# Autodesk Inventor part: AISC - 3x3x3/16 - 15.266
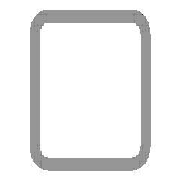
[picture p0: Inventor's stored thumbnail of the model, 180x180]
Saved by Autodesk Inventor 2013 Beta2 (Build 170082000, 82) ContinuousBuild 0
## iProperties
IsCustomPart: 1
Created: 2011-01
Part Number: AISC - 3x3x3/16 - 15.266
Material: Steel, Mild
Description: Tube
Document SubType Name: Modeling
Standard: ANSI
Designer: Beta-8540w
Standards Organization: ANSI
Language: en-US
Size Designation: 3x3x3/16
Categories: <MemberInstance><Categories><Category DisplayName="Structural Shapes" InternalName="089c4875-fa83-4c05-b084-43b9cc11f5ed" Mnemonic="GRDR"><CategoryParameter Dis
Stock Number: 3x3x3/16
Density: 7.86 g/cm^3
_CCFamilyMember: 9
_CCFamilyDisplayName: ANSI AISC (Square) - Tube
_FrameMemberDoc: Frame Member File
_Version: 15.0.0
_GetPNFromCC: 1
G_L: 15.266 in
G_W: 3.000 in
G_H: 3.000 in
+FD2FA98F-6131-4ED7-8715-576CB225FAC2+CUTDETAIL1: Cut
+6EE38D32-1A45-4B16-9B4C-47EFE8477959+CUTDETAIL2: Cut
Author: Beta-8540w
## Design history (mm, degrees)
node "Start plane"
node "End plane"
sketch "Sketch"
  geometry: L1 (-38.1, -28.575)-(-38.1, 28.575); L2 (-28.575, 38.1)-(28.575, 38.1); L3 (38.1, 28.575)-(38.1, -28.575); L4 (28.575, -38.1)-(-28.575, -38.1); L5 (-28.575, 33.337)-(28.575, 33.338); L6 (33.338, 28.575)-(33.338, -28.575); L7 (28.575, -33.337)-(-28.575, -33.338); L8 (-33.338, -28.575)-(-33.338, 28.575); L9 (0, 56.102)-(0, -56.102) reference; L10 (-56.102, 0)-(56.102, 0) reference; A1 r 9.525 centre (-28.575, -28.575) between (-38.1, -28.575) and (-28.575, -38.1); A2 r 9.525 centre (-28.575, 28.575) between (-28.575, 38.1) and (-38.1, 28.575); A3 r 9.525 centre (28.575, 28.575) between (38.1, 28.575) and (28.575, 38.1); A4 r 9.525 centre (28.575, -28.575) between (28.575, -38.1) and (38.1, -28.575); A5 r 4.763 centre (-28.575, 28.575) between (-28.575, 33.337) and (-33.338, 28.575); A6 r 4.763 centre (28.575, 28.575) between (33.338, 28.575) and (28.575, 33.338); A7 r 4.763 centre (28.575, -28.575) between (28.575, -33.337) and (33.338, -28.575); A8 r 4.763 centre (-28.575, -28.575) between (-33.338, -28.575) and (-28.575, -33.338)
  constraints: 16 end point, 16 point on circle, 8 centre point, 8 tangent, 4 parallel, 3 equal radius, 2 perpendicular, 7 other
  dimensions: "d10" = 76.2 distance between parallel lines of L2 L4 (= G_H); "d11" = 76.2 distance between parallel lines of L1 L3 (= G_W); "d12" = 4.7625 distance between parallel lines of L3 L6 (= G_T); "d15" = 38.1 distance between parallel lines of L2 L10 (= 0.5 x d10); "d16" = 38.1 distance between parallel lines of L9 L3 (= 0.5 x d11); "d17" = 9.525 radius of A1 (= G_IR)
extrude "Body" new body sketch "Sketch" stored distance "d3" = 387.75605 (= G_L); taper "d4" = 0 deg
node "Driven Length"
  sketch "Sketch3"
    geometry: L1 (0, 0)-(10, 0) reference
    constraints: 2 end point, 1 horizontal
  workplane "Work Plane3"
  sketch "Sketch4"
    geometry: L1 (-2, 31.109)-(12, 31.109) reference; L2 (-2, 418.865)-(12, 418.865) reference
    dimensions: "d19" = 387.75605 distance between parallel lines of L1 L2 (derived)
workplane "Work Plane4"
split "Split1"
workplane "Work Plane5"
split "Split2"
body "Solid1"
other parameters: "G_W" = 76.2 [user parameter; used in 1 equation term], "G_H" = 76.2 [user parameter; used in 1 equation term], "G_T" = 4.7625 [user parameter; used in 1 equation term], "G_IR" = 9.525 [user parameter; used in 1 equation term], "G_L" = 387.75605 (= d19) [user parameter; used in 1 equation term], "G_OFFSET_START" = -31.10852 [user parameter; used in 1 equation term], "G_OFFSET_END" = -31.10852 [user parameter; used in 1 equation term], "d13" = 31.10852 (= -G_OFFSET_START), "d14" = 418.86457 (= G_OFFSET_END + B_L), "B_L" = 449.97309 [user parameter; used in 1 equation term], "d18" = 90 deg
